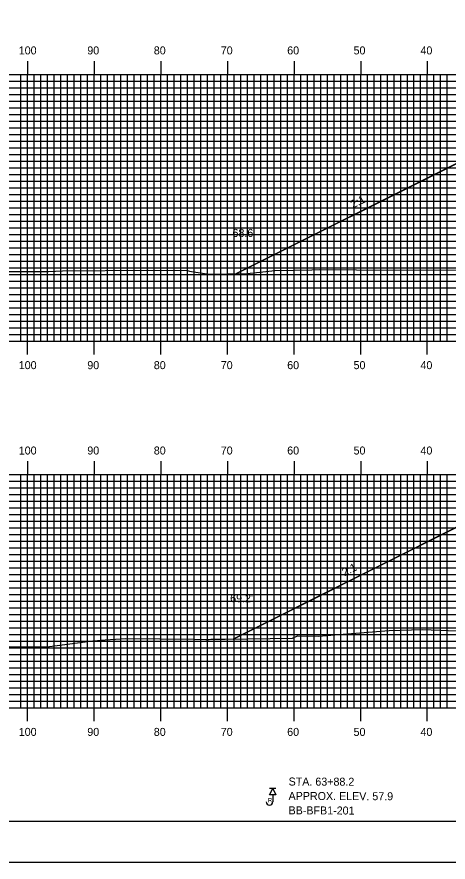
# Model space of a CAD drawing. Extents: x 1758643 to 1758986, y 442591 to 442811.
# Drawn here: x 1758707.1 to 1758771.8, y 442590.5 to 442717.3 of the extents above; entities that cross this region are included whole.
import ezdxf

# ---------------------------------------------------------------- set-up
doc = ezdxf.new("R2010")
doc.units = 0
for name, color, linetype in [('ANNOTATION', 7, 'Continuous'), ('BORDER', 7, 'Continuous'), ('BORING - REFUSAL', 7, 'Continuous'), ('D_Roadway_Centerline', 7, 'Continuous'), ('D_Roadway_SlopeLines', 7, 'Continuous'), ('D_Text_Standard', 7, 'Continuous'), ('H_V ANNOTATION', 7, 'Continuous'), ('MAJOR', 7, 'Continuous'), ('MINOR', 7, 'Continuous'), ('PLOT BOUNDARY', 7, 'Continuous'), ('S_Roadway_Centerline', 7, 'Continuous')]:
    doc.layers.add(name, color=color, linetype=linetype)

msp = doc.modelspace()

# ---------------------------------------------------------------- linework, layer by layer
at = {"layer": 'BORDER'}
msp.add_lwpolyline([(1758659.05, 442596.67), (1758979.05, 442596.67), (1758979.05, 442806.67), (1758659.05, 442806.67)], close=True, dxfattribs=at)
at = {"layer": 'BORING - REFUSAL'}
for p, q in [((1758745.93, 442601.59), (1758744.97, 442601.59)), ((1758745.45, 442600.63), (1758745.45, 442599.57))]:
    msp.add_line(p, q, dxfattribs=at)
msp.add_lwpolyline([(1758745.45, 442601.59), (1758745.93, 442600.63), (1758744.97, 442600.63)], close=True, dxfattribs=at)
msp.add_arc((1758744.96, 442599.57), 0.485, 180, 0, dxfattribs=at)
at = {"layer": 'D_Roadway_Centerline'}
for points in [[(1758740.03, 442678.79), (1758773.89, 442695.72), (1758778.64, 442698.1), (1758781.64, 442698.22), (1758789.64, 442698.54), (1758796.65, 442698.68), (1758808.65, 442698.92), (1758820.65, 442699.05), (1758821.41, 442699.06), (1758830.1, 442698.81), (1758833.42, 442698.71), (1758837.57, 442698.54), (1758841.42, 442698.39), (1758843.56, 442698.3), (1758844.42, 442698.27), (1758845.53, 442697.71), (1758849.39, 442695.78), (1758850.9, 442695.02), (1758852.29, 442694.33), (1758866.5, 442687.22), (1758881.57, 442679.68)], [(1758739.49, 442623.98), (1758771.89, 442640.18), (1758776.64, 442642.56), (1758779.64, 442642.68), (1758787.64, 442643), (1758796.65, 442643.18), (1758808.65, 442643.42), (1758820.65, 442643.31), (1758823.83, 442643.29), (1758830.59, 442642.96), (1758835.85, 442642.7), (1758839.13, 442642.54), (1758842.23, 442642.38), (1758843.87, 442642.3), (1758845.59, 442642.22), (1758846.87, 442642.15), (1758848.82, 442641.18), (1758852.31, 442639.43), (1758854.14, 442638.52), (1758855.8, 442637.68), (1758868.84, 442631.16), (1758878.74, 442626.2), (1758880.26, 442625.44), (1758882.72, 442624.21)]]:
    msp.add_lwpolyline(points, dxfattribs=at)
at = {"layer": 'D_Roadway_SlopeLines'}
for points in [[(1758778.64, 442698.1), (1758740.03, 442678.79)], [(1758776.64, 442642.56), (1758739.49, 442623.98)]]:
    msp.add_lwpolyline(points, dxfattribs=at)
at = {"layer": 'MAJOR'}
for p, q in [((1758708.65, 442710.67), (1758708.65, 442708.67)), ((1758718.65, 442710.67), (1758718.65, 442708.67)), ((1758728.65, 442710.67), (1758728.65, 442708.67)), ((1758738.65, 442710.67), (1758738.65, 442708.67)), ((1758748.65, 442710.67), (1758748.65, 442708.67)), ((1758758.65, 442710.67), (1758758.65, 442708.67)), ((1758768.65, 442710.67), (1758768.65, 442708.67)), ((1758668.65, 442708.67), (1758948.65, 442708.67)), ((1758668.65, 442708.67), (1758948.65, 442708.67)), ((1758708.65, 442668.67), (1758708.65, 442708.67)), ((1758718.65, 442668.67), (1758718.65, 442708.67)), ((1758728.65, 442668.67), (1758728.65, 442708.67)), ((1758738.65, 442668.67), (1758738.65, 442708.67)), ((1758748.65, 442668.67), (1758748.65, 442708.67)), ((1758758.65, 442668.67), (1758758.65, 442708.67)), ((1758768.65, 442668.67), (1758768.65, 442708.67)), ((1758668.65, 442703.67), (1758948.65, 442703.67)), ((1758668.65, 442698.67), (1758948.65, 442698.67)), ((1758668.65, 442693.67), (1758948.65, 442693.67)), ((1758668.65, 442688.67), (1758948.65, 442688.67)), ((1758668.65, 442683.67), (1758948.65, 442683.67)), ((1758668.65, 442678.67), (1758948.65, 442678.67)), ((1758668.65, 442673.67), (1758948.65, 442673.67)), ((1758668.65, 442668.67), (1758948.65, 442668.67)), ((1758668.65, 442668.67), (1758948.65, 442668.67)), ((1758708.65, 442666.66), (1758708.65, 442668.67)), ((1758718.65, 442666.66), (1758718.65, 442668.67)), ((1758728.65, 442666.66), (1758728.65, 442668.67)), ((1758738.65, 442666.66), (1758738.65, 442668.67)), ((1758748.65, 442666.66), (1758748.65, 442668.67)), ((1758758.65, 442666.66), (1758758.65, 442668.67)), ((1758768.65, 442666.66), (1758768.65, 442668.67)), ((1758708.65, 442650.67), (1758708.65, 442648.67)), ((1758718.65, 442650.67), (1758718.65, 442648.67)), ((1758728.65, 442650.67), (1758728.65, 442648.67)), ((1758738.65, 442650.67), (1758738.65, 442648.67)), ((1758748.65, 442650.67), (1758748.65, 442648.67)), ((1758758.65, 442650.67), (1758758.65, 442648.67)), ((1758768.65, 442650.67), (1758768.65, 442648.67)), ((1758668.65, 442648.67), (1758948.65, 442648.67)), ((1758668.65, 442648.67), (1758948.65, 442648.67)), ((1758708.65, 442613.67), (1758708.65, 442648.67)), ((1758718.65, 442613.67), (1758718.65, 442648.67)), ((1758728.65, 442613.67), (1758728.65, 442648.67)), ((1758738.65, 442613.67), (1758738.65, 442648.67)), ((1758748.65, 442613.67), (1758748.65, 442648.67)), ((1758758.65, 442613.67), (1758758.65, 442648.67)), ((1758768.65, 442613.67), (1758768.65, 442648.67)), ((1758668.65, 442643.67), (1758948.65, 442643.67)), ((1758668.65, 442638.67), (1758948.65, 442638.67)), ((1758668.65, 442633.67), (1758948.65, 442633.67)), ((1758668.65, 442628.67), (1758948.65, 442628.67)), ((1758668.65, 442623.67), (1758948.65, 442623.67)), ((1758668.65, 442618.67), (1758948.65, 442618.67)), ((1758668.65, 442613.67), (1758948.65, 442613.67)), ((1758668.65, 442613.67), (1758948.65, 442613.67)), ((1758708.65, 442611.66), (1758708.65, 442613.67)), ((1758718.65, 442611.66), (1758718.65, 442613.67)), ((1758728.65, 442611.66), (1758728.65, 442613.67)), ((1758738.65, 442611.66), (1758738.65, 442613.67)), ((1758748.65, 442611.66), (1758748.65, 442613.67)), ((1758758.65, 442611.66), (1758758.65, 442613.67)), ((1758768.65, 442611.66), (1758768.65, 442613.67))]:
    msp.add_line(p, q, dxfattribs=at)
at = {"layer": 'MINOR'}
for p, q in [((1758707.65, 442668.67), (1758707.65, 442708.67)), ((1758709.65, 442668.67), (1758709.65, 442708.67)), ((1758710.65, 442668.67), (1758710.65, 442708.67)), ((1758711.65, 442668.67), (1758711.65, 442708.67)), ((1758712.65, 442668.67), (1758712.65, 442708.67)), ((1758713.65, 442668.67), (1758713.65, 442708.67)), ((1758714.65, 442668.67), (1758714.65, 442708.67)), ((1758715.65, 442668.67), (1758715.65, 442708.67)), ((1758716.65, 442668.67), (1758716.65, 442708.67)), ((1758717.65, 442668.67), (1758717.65, 442708.67)), ((1758719.65, 442668.67), (1758719.65, 442708.67)), ((1758720.65, 442668.67), (1758720.65, 442708.67)), ((1758721.65, 442668.67), (1758721.65, 442708.67)), ((1758722.65, 442668.67), (1758722.65, 442708.67)), ((1758723.65, 442668.67), (1758723.65, 442708.67)), ((1758724.65, 442668.67), (1758724.65, 442708.67)), ((1758725.65, 442668.67), (1758725.65, 442708.67)), ((1758726.65, 442668.67), (1758726.65, 442708.67)), ((1758727.65, 442668.67), (1758727.65, 442708.67)), ((1758729.65, 442668.67), (1758729.65, 442708.67)), ((1758730.65, 442668.67), (1758730.65, 442708.67)), ((1758731.65, 442668.67), (1758731.65, 442708.67)), ((1758732.65, 442668.67), (1758732.65, 442708.67)), ((1758733.65, 442668.67), (1758733.65, 442708.67)), ((1758734.65, 442668.67), (1758734.65, 442708.67)), ((1758735.65, 442668.67), (1758735.65, 442708.67)), ((1758736.65, 442668.67), (1758736.65, 442708.67)), ((1758737.65, 442668.67), (1758737.65, 442708.67)), ((1758739.65, 442668.67), (1758739.65, 442708.67)), ((1758740.65, 442668.67), (1758740.65, 442708.67)), ((1758741.65, 442668.67), (1758741.65, 442708.67)), ((1758742.65, 442668.67), (1758742.65, 442708.67)), ((1758743.65, 442668.67), (1758743.65, 442708.67)), ((1758744.65, 442668.67), (1758744.65, 442708.67)), ((1758745.65, 442668.67), (1758745.65, 442708.67)), ((1758746.65, 442668.67), (1758746.65, 442708.67)), ((1758747.65, 442668.67), (1758747.65, 442708.67)), ((1758749.65, 442668.67), (1758749.65, 442708.67)), ((1758750.65, 442668.67), (1758750.65, 442708.67)), ((1758751.65, 442668.67), (1758751.65, 442708.67)), ((1758752.65, 442668.67), (1758752.65, 442708.67)), ((1758753.65, 442668.67), (1758753.65, 442708.67)), ((1758754.65, 442668.67), (1758754.65, 442708.67)), ((1758755.65, 442668.67), (1758755.65, 442708.67)), ((1758756.65, 442668.67), (1758756.65, 442708.67)), ((1758757.65, 442668.67), (1758757.65, 442708.67)), ((1758759.65, 442668.67), (1758759.65, 442708.67)), ((1758760.65, 442668.67), (1758760.65, 442708.67)), ((1758761.65, 442668.67), (1758761.65, 442708.67)), ((1758762.65, 442668.67), (1758762.65, 442708.67)), ((1758763.65, 442668.67), (1758763.65, 442708.67)), ((1758764.65, 442668.67), (1758764.65, 442708.67)), ((1758765.65, 442668.67), (1758765.65, 442708.67)), ((1758766.65, 442668.67), (1758766.65, 442708.67)), ((1758767.65, 442668.67), (1758767.65, 442708.67)), ((1758769.65, 442668.67), (1758769.65, 442708.67)), ((1758770.65, 442668.67), (1758770.65, 442708.67)), ((1758771.65, 442668.67), (1758771.65, 442708.67)), ((1758668.65, 442707.67), (1758948.65, 442707.67)), ((1758668.65, 442706.67), (1758948.65, 442706.67)), ((1758668.65, 442705.67), (1758948.65, 442705.67)), ((1758668.65, 442704.67), (1758948.65, 442704.67)), ((1758668.65, 442702.67), (1758948.65, 442702.67)), ((1758668.65, 442701.67), (1758948.65, 442701.67)), ((1758668.65, 442700.67), (1758948.65, 442700.67)), ((1758668.65, 442699.67), (1758948.65, 442699.67)), ((1758668.65, 442697.67), (1758948.65, 442697.67)), ((1758668.65, 442696.67), (1758948.65, 442696.67)), ((1758668.65, 442695.67), (1758948.65, 442695.67)), ((1758668.65, 442694.67), (1758948.65, 442694.67)), ((1758668.65, 442692.67), (1758948.65, 442692.67)), ((1758668.65, 442691.67), (1758948.65, 442691.67)), ((1758668.65, 442690.67), (1758948.65, 442690.67)), ((1758668.65, 442689.67), (1758948.65, 442689.67)), ((1758668.65, 442687.67), (1758948.65, 442687.67)), ((1758668.65, 442686.67), (1758948.65, 442686.67)), ((1758668.65, 442685.67), (1758948.65, 442685.67)), ((1758668.65, 442684.67), (1758948.65, 442684.67)), ((1758668.65, 442682.67), (1758948.65, 442682.67)), ((1758668.65, 442681.67), (1758948.65, 442681.67)), ((1758668.65, 442680.67), (1758948.65, 442680.67)), ((1758668.65, 442679.67), (1758948.65, 442679.67)), ((1758668.65, 442677.67), (1758948.65, 442677.67)), ((1758668.65, 442676.67), (1758948.65, 442676.67)), ((1758668.65, 442675.67), (1758948.65, 442675.67)), ((1758668.65, 442674.67), (1758948.65, 442674.67)), ((1758668.65, 442672.67), (1758948.65, 442672.67)), ((1758668.65, 442671.67), (1758948.65, 442671.67)), ((1758668.65, 442670.67), (1758948.65, 442670.67)), ((1758668.65, 442669.67), (1758948.65, 442669.67)), ((1758707.65, 442613.67), (1758707.65, 442648.67)), ((1758709.65, 442613.67), (1758709.65, 442648.67)), ((1758710.65, 442613.67), (1758710.65, 442648.67)), ((1758711.65, 442613.67), (1758711.65, 442648.67)), ((1758712.65, 442613.67), (1758712.65, 442648.67)), ((1758713.65, 442613.67), (1758713.65, 442648.67)), ((1758714.65, 442613.67), (1758714.65, 442648.67)), ((1758715.65, 442613.67), (1758715.65, 442648.67)), ((1758716.65, 442613.67), (1758716.65, 442648.67)), ((1758717.65, 442613.67), (1758717.65, 442648.67)), ((1758719.65, 442613.67), (1758719.65, 442648.67)), ((1758720.65, 442613.67), (1758720.65, 442648.67)), ((1758721.65, 442613.67), (1758721.65, 442648.67)), ((1758722.65, 442613.67), (1758722.65, 442648.67)), ((1758723.65, 442613.67), (1758723.65, 442648.67)), ((1758724.65, 442613.67), (1758724.65, 442648.67)), ((1758725.65, 442613.67), (1758725.65, 442648.67)), ((1758726.65, 442613.67), (1758726.65, 442648.67)), ((1758727.65, 442613.67), (1758727.65, 442648.67)), ((1758729.65, 442613.67), (1758729.65, 442648.67)), ((1758730.65, 442613.67), (1758730.65, 442648.67)), ((1758731.65, 442613.67), (1758731.65, 442648.67)), ((1758732.65, 442613.67), (1758732.65, 442648.67)), ((1758733.65, 442613.67), (1758733.65, 442648.67)), ((1758734.65, 442613.67), (1758734.65, 442648.67)), ((1758735.65, 442613.67), (1758735.65, 442648.67)), ((1758736.65, 442613.67), (1758736.65, 442648.67)), ((1758737.65, 442613.67), (1758737.65, 442648.67)), ((1758739.65, 442613.67), (1758739.65, 442648.67)), ((1758740.65, 442613.67), (1758740.65, 442648.67)), ((1758741.65, 442613.67), (1758741.65, 442648.67)), ((1758742.65, 442613.67), (1758742.65, 442648.67)), ((1758743.65, 442613.67), (1758743.65, 442648.67)), ((1758744.65, 442613.67), (1758744.65, 442648.67)), ((1758745.65, 442613.67), (1758745.65, 442648.67)), ((1758746.65, 442613.67), (1758746.65, 442648.67)), ((1758747.65, 442613.67), (1758747.65, 442648.67)), ((1758749.65, 442613.67), (1758749.65, 442648.67)), ((1758750.65, 442613.67), (1758750.65, 442648.67)), ((1758751.65, 442613.67), (1758751.65, 442648.67)), ((1758752.65, 442613.67), (1758752.65, 442648.67)), ((1758753.65, 442613.67), (1758753.65, 442648.67)), ((1758754.65, 442613.67), (1758754.65, 442648.67)), ((1758755.65, 442613.67), (1758755.65, 442648.67)), ((1758756.65, 442613.67), (1758756.65, 442648.67)), ((1758757.65, 442613.67), (1758757.65, 442648.67)), ((1758759.65, 442613.67), (1758759.65, 442648.67)), ((1758760.65, 442613.67), (1758760.65, 442648.67)), ((1758761.65, 442613.67), (1758761.65, 442648.67)), ((1758762.65, 442613.67), (1758762.65, 442648.67)), ((1758763.65, 442613.67), (1758763.65, 442648.67)), ((1758764.65, 442613.67), (1758764.65, 442648.67)), ((1758765.65, 442613.67), (1758765.65, 442648.67)), ((1758766.65, 442613.67), (1758766.65, 442648.67)), ((1758767.65, 442613.67), (1758767.65, 442648.67)), ((1758769.65, 442613.67), (1758769.65, 442648.67)), ((1758770.65, 442613.67), (1758770.65, 442648.67)), ((1758771.65, 442613.67), (1758771.65, 442648.67)), ((1758668.65, 442647.67), (1758948.65, 442647.67)), ((1758668.65, 442646.67), (1758948.65, 442646.67)), ((1758668.65, 442645.67), (1758948.65, 442645.67)), ((1758668.65, 442644.67), (1758948.65, 442644.67)), ((1758668.65, 442642.67), (1758948.65, 442642.67)), ((1758668.65, 442641.67), (1758948.65, 442641.67)), ((1758668.65, 442640.67), (1758948.65, 442640.67)), ((1758668.65, 442639.67), (1758948.65, 442639.67)), ((1758668.65, 442637.67), (1758948.65, 442637.67)), ((1758668.65, 442636.67), (1758948.65, 442636.67)), ((1758668.65, 442635.67), (1758948.65, 442635.67)), ((1758668.65, 442634.67), (1758948.65, 442634.67)), ((1758668.65, 442632.67), (1758948.65, 442632.67)), ((1758668.65, 442631.67), (1758948.65, 442631.67)), ((1758668.65, 442630.67), (1758948.65, 442630.67)), ((1758668.65, 442629.67), (1758948.65, 442629.67)), ((1758668.65, 442627.67), (1758948.65, 442627.67)), ((1758668.65, 442626.67), (1758948.65, 442626.67)), ((1758668.65, 442625.67), (1758948.65, 442625.67)), ((1758668.65, 442624.67), (1758948.65, 442624.67)), ((1758668.65, 442622.67), (1758948.65, 442622.67)), ((1758668.65, 442621.67), (1758948.65, 442621.67)), ((1758668.65, 442620.67), (1758948.65, 442620.67)), ((1758668.65, 442619.67), (1758948.65, 442619.67)), ((1758668.65, 442617.67), (1758948.65, 442617.67)), ((1758668.65, 442616.67), (1758948.65, 442616.67)), ((1758668.65, 442615.67), (1758948.65, 442615.67)), ((1758668.65, 442614.67), (1758948.65, 442614.67))]:
    msp.add_line(p, q, dxfattribs=at)
at = {"layer": 'PLOT BOUNDARY'}
msp.add_lwpolyline([(1758642.86, 442590.55), (1758982.86, 442590.55), (1758982.86, 442810.55), (1758642.86, 442810.55)], close=True, dxfattribs=at)
at = {"layer": 'S_Roadway_Centerline'}
for points in [[(1758668.65, 442679.55), (1758669.14, 442679.55), (1758689.52, 442679.16), (1758696.42, 442679.09), (1758711.78, 442679.13), (1758713.91, 442679.19), (1758726.74, 442679.3), (1758732.65, 442679.27), (1758732.97, 442679.14), (1758735.85, 442678.72), (1758741.57, 442678.82), (1758743.51, 442678.99), (1758745.78, 442679.24), (1758751.32, 442679.36), (1758752.54, 442679.39), (1758758, 442679.38), (1758774.87, 442679.33)], [(1758668.65, 442622.36), (1758672.79, 442622.4), (1758678.47, 442622.41), (1758683.44, 442622.69), (1758685.54, 442622.94), (1758711.43, 442622.82), (1758711.56, 442622.82), (1758711.97, 442622.88), (1758718.44, 442623.75), (1758719.15, 442623.78), (1758720.3, 442623.9), (1758723.42, 442624.1), (1758733.59, 442623.99), (1758735.4, 442623.93), (1758735.74, 442623.95), (1758735.91, 442623.92), (1758736.14, 442623.97), (1758738.31, 442623.96), (1758748.42, 442624.13), (1758749.19, 442624.5), (1758752.27, 442624.44), (1758762.94, 442625.29), (1758767.94, 442625.41), (1758774.37, 442625.17)]]:
    msp.add_lwpolyline(points, dxfattribs=at)

# ---------------------------------------------------------------- texts
at = {"layer": 'ANNOTATION'}
for p in [(1758757.48, 442688.55), (1758756.21, 442633.38)]:
    msp.add_text('2:1', height=1.2, rotation=26.5651, dxfattribs=at).set_placement(p)
at = {"layer": 'BORING - REFUSAL'}
for s, p in [('STA. 63+88.2', (1758747.83, 442602.03)), ('APPROX. ELEV. 57.9', (1758747.82, 442599.87)), ('BB-BFB1-201', (1758747.82, 442597.71))]:
    msp.add_text(s, height=1.2, rotation=359.8142, dxfattribs=at).set_placement(p)
msp.add_text('R', height=0.64, dxfattribs=at).set_placement((1758744.74, 442599.51))
at = {"layer": 'D_Text_Standard'}
for s, p in [("68.6'", (1758739.41, 442684.3)), ("69.2'", (1758739.06, 442629.52))]:
    msp.add_text(s, height=1.2, dxfattribs=at).set_placement(p)
at = {"layer": 'H_V ANNOTATION'}
for s, p in [('100', (1758707.33, 442711.67)), ('90', (1758717.62, 442711.67)), ('80', (1758727.6, 442711.67)), ('70', (1758737.65, 442711.67)), ('60', (1758747.62, 442711.67)), ('50', (1758757.58, 442711.67)), ('40', (1758767.62, 442711.67)), ('100', (1758707.33, 442664.47)), ('90', (1758717.62, 442664.47)), ('80', (1758727.6, 442664.47)), ('70', (1758737.65, 442664.47)), ('60', (1758747.62, 442664.47)), ('50', (1758757.58, 442664.47)), ('40', (1758767.62, 442664.47)), ('100', (1758707.33, 442651.67)), ('90', (1758717.62, 442651.67)), ('80', (1758727.6, 442651.67)), ('70', (1758737.65, 442651.67)), ('60', (1758747.62, 442651.67)), ('50', (1758757.58, 442651.67)), ('40', (1758767.62, 442651.67)), ('100', (1758707.33, 442609.47)), ('90', (1758717.62, 442609.47)), ('80', (1758727.6, 442609.47)), ('70', (1758737.65, 442609.47)), ('60', (1758747.62, 442609.47)), ('50', (1758757.58, 442609.47)), ('40', (1758767.62, 442609.47))]:
    msp.add_text(s, height=1.2, dxfattribs=at).set_placement(p)

doc.saveas('drawing.dxf')
